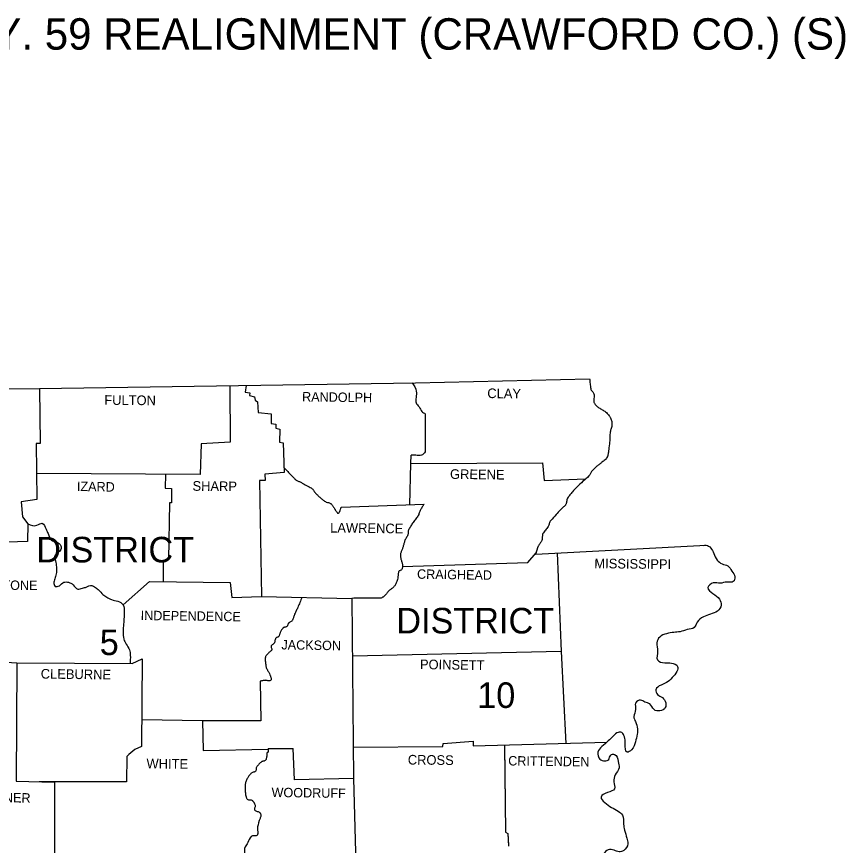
# Model space of a CAD drawing. Extents: x 6028666 to 6031787, y 5366484 to 5368484.
# Drawn here: x 6031401.8 to 6031771, y 5368078.3 to 5368447.7 of the extents above; entities that cross this region are included whole.
import ezdxf

# ---------------------------------------------------------------- set-up
doc = ezdxf.new("R2010")
doc.units = 0
doc.layers.add('2', color=7, linetype='Continuous')
doc.layers.add('R_Border', color=7, linetype='Continuous')

msp = doc.modelspace()

# ---------------------------------------------------------------- linework, layer by layer
at = {"layer": '2'}
for p, q in [((6031577.46, 5368248.49), (6031577.55, 5368252.19)), ((6031633.05, 5368208.19), (6031634.13, 5368211.51)), ((6031513.85, 5368121.6), (6031525.03, 5368121.6))]:
    msp.add_line(p, q, dxfattribs=at)
for points in [[(6031108.45, 5368281.69), (6031270.15, 5368281.59), (6031412.05, 5368281.89), (6031579.45, 5368284.49), (6031657.05, 5368286.29)], [(6031412.05, 5368281.89), (6031412.25, 5368257.49), (6031410.55, 5368257.39), (6031410.85, 5368232.49), (6031403.85, 5368231.49), (6031404.45, 5368224.79), (6031406.85, 5368221.69), (6031406.65, 5368213.79), (6031393.05, 5368213.29), (6031392.55, 5368201.09), (6031380.15, 5368200.69), (6031379.55, 5368185.89), (6031380.25, 5368184.69), (6031380.55, 5368161.09), (6031401.95, 5368159.69), (6031401.65, 5368107), (6031418.65, 5368106.5), (6031418.65, 5368052.9), (6031405.25, 5368051.9), (6031404.25, 5368040.1), (6031381.75, 5368040)], [(6031496.75, 5368283.21), (6031496.95, 5368257.99), (6031483.95, 5368257.29), (6031483.55, 5368243.69), (6031410.71, 5368244.1)], [(6031504.03, 5368283.32), (6031503.65, 5368280.29), (6031505.65, 5368279.99), (6031505.55, 5368278.79), (6031507.85, 5368278.29), (6031508.05, 5368276.69), (6031509.15, 5368275.99), (6031509.45, 5368271.19), (6031515.15, 5368270.59), (6031515.15, 5368266.29), (6031517.25, 5368265.99), (6031517.25, 5368264.29), (6031519.05, 5368263.79), (6031518.95, 5368257.99), (6031520.55, 5368257.69), (6031520.95, 5368244.59), (6031512.45, 5368243.79), (6031512.55, 5368240.99), (6031509.95, 5368240.89), (6031510.85, 5368189.29), (6031551.15, 5368188.39), (6031551.85, 5368108.2), (6031525.55, 5368107.5), (6031525.03, 5368121.6)], [(6031583.85, 5368270.69), (6031583.85, 5368253.79)], [(6031577.03, 5368230.16), (6031577.46, 5368248.49), (6031577.55, 5368248.49), (6031636.05, 5368248.79), (6031636.85, 5368240.99), (6031655.2, 5368241.66)], [(6031468.17, 5368243.78), (6031467.95, 5368237.59), (6031470.75, 5368237.39), (6031470.85, 5368230.99), (6031469.85, 5368230.99), (6031469.45, 5368205.79), (6031467.15, 5368204.79), (6031467.15, 5368195.91)], [(6031546.45, 5368229.09), (6031583.32, 5368230.38)], [(6031633.05, 5368208.19), (6031708.95, 5368212.09)], [(6031573.71, 5368202.68), (6031629.55, 5368204.49), (6031633.22, 5368208.72)], [(6031642.63, 5368208.69), (6031644.35, 5368164.79), (6031646.39, 5368123.83)], [(6031449.35, 5368185.51), (6031460.95, 5368195.99), (6031496.95, 5368195.49), (6031497.65, 5368188.79), (6031510.85, 5368189.29)], [(6031564.25, 5368188.59), (6031552.05, 5368188.59), (6031551.15, 5368188.39)], [(6031644.35, 5368164.79), (6031551.38, 5368162.67)], [(6031401.95, 5368159.69), (6031453.35, 5368159.39), (6031457.75, 5368161.49), (6031457.45, 5368122.4), (6031454.45, 5368121.1), (6031451.75, 5368118.8), (6031450.85, 5368117.9), (6031450.75, 5368106.7), (6031411.85, 5368106.7)], [(6031510.35, 5368151.5), (6031510.55, 5368133.9), (6031484.55, 5368133.8), (6031457.54, 5368134.3)], [(6031484.55, 5368133.8), (6031484.95, 5368120.7), (6031513.85, 5368121.21)], [(6031551.73, 5368122.19), (6031591.65, 5368122.4), (6031591.75, 5368123.8), (6031605.15, 5368124.8), (6031605.15, 5368122.7), (6031664.72, 5368124.33)], [(6031619.15, 5368123.08), (6031619.65, 5368084.2), (6031620.55, 5368083.6), (6031620.87, 5368078.06)], [(6031513.85, 5368121.6), (6031513.85, 5368119.9), (6031513.35, 5368119.8)], [(6031619.15, 5368122.7), (6031619.65, 5368084.2), (6031620.55, 5368083.6), (6031620.85, 5368078.4)], [(6031619.15, 5368122.7), (6031619.65, 5368084.2), (6031620.55, 5368083.6), (6031620.85, 5368078.4)], [(6031619.15, 5368122.7), (6031619.65, 5368084.2), (6031620.55, 5368083.6), (6031620.85, 5368078.4)], [(6031619.15, 5368122.7), (6031619.65, 5368084.2), (6031620.55, 5368083.6), (6031620.85, 5368078.4)], [(6031551.85, 5368108.2), (6031553.35, 5368053.4), (6031529.55, 5368053.3), (6031529.45, 5368051.1), (6031522.55, 5368050.7), (6031521.95, 5368039.3), (6031512.47, 5368039.3)]]:
    msp.add_lwpolyline(points, dxfattribs=at)
for points in [[(6031657.05, 5368286.29), (6031657.14, 5368285.19), (6031657.25, 5368284.09), (6031657.39, 5368282.99), (6031657.55, 5368281.89), (6031657.79, 5368281.27), (6031658.19, 5368280.71), (6031658.63, 5368280.17), (6031658.95, 5368279.59), (6031659.08, 5368278.58), (6031658.95, 5368277.48), (6031658.88, 5368276.39), (6031658.95, 5368275.88), (6031659.15, 5368275.39), (6031659.91, 5368274.41), (6031660.85, 5368273.59), (6031661.57, 5368273.12), (6031662.31, 5368272.7), (6031663.04, 5368272.28), (6031663.75, 5368271.79), (6031665.19, 5368270.51), (6031665.81, 5368269.76), (6031666.09, 5368269.35), (6031666.35, 5368268.89), (6031666.71, 5368268.05), (6031666.93, 5368267.19), (6031667, 5368266.34), (6031666.95, 5368265.49), (6031666.78, 5368264.62), (6031666.53, 5368263.75), (6031666.3, 5368262.87), (6031666.15, 5368261.99), (6031666.1, 5368261.02), (6031666.06, 5368260.04), (6031666.02, 5368259.07), (6031665.95, 5368258.09), (6031665.55, 5368254.69), (6031665.36, 5368253.13), (6031665.21, 5368252.35), (6031665.1, 5368251.97), (6031664.95, 5368251.59), (6031663.91, 5368250.21), (6031662.55, 5368249.09), (6031661.98, 5368248.64), (6031661.4, 5368248.2), (6031660.82, 5368247.76), (6031660.25, 5368247.29), (6031658.15, 5368245.19), (6031657.76, 5368244.65), (6031657.42, 5368244.07), (6031657.07, 5368243.5), (6031656.65, 5368242.99), (6031654.05, 5368240.59), (6031651.45, 5368238.09), (6031649.35, 5368235.89), (6031648.78, 5368235.23), (6031648.24, 5368234.54), (6031647.74, 5368233.82), (6031647.25, 5368233.09), (6031646.95, 5368232.34), (6031646.8, 5368231.51), (6031646.63, 5368230.7), (6031646.48, 5368230.33), (6031646.25, 5368229.99), (6031645.7, 5368229.42), (6031645.11, 5368228.89), (6031644.51, 5368228.36), (6031643.95, 5368227.79), (6031642.15, 5368225.79), (6031639.75, 5368223.09), (6031639.36, 5368222.48), (6031639.09, 5368221.78), (6031638.85, 5368221.07), (6031638.55, 5368220.39), (6031638.02, 5368219.6), (6031637.39, 5368218.85), (6031636.77, 5368218.1), (6031636.25, 5368217.29), (6031636.04, 5368216.58), (6031635.98, 5368215.8), (6031635.93, 5368215.02), (6031635.75, 5368214.29), (6031635.43, 5368213.67), (6031635.03, 5368213.08), (6031634.62, 5368212.49), (6031634.25, 5368211.89), (6031634.13, 5368211.51)], [(6031578.04, 5368284.47), (6031579.85, 5368280.69), (6031579.75, 5368277.99), (6031579.75, 5368275.49), (6031581.05, 5368273.79), (6031582.35, 5368271.69), (6031583.85, 5368270.69)], [(6031583.85, 5368253.79), (6031582.15, 5368252.19), (6031579.65, 5368252.19), (6031577.55, 5368252.19)], [(6031520.89, 5368246.7), (6031522.56, 5368244.94), (6031524.25, 5368243.19), (6031524.49, 5368242.95), (6031525.18, 5368242.22), (6031525.65, 5368241.75), (6031525.9, 5368241.51), (6031526.02, 5368241.4), (6031526.15, 5368241.29), (6031526.66, 5368240.95), (6031527.22, 5368240.7), (6031527.8, 5368240.46), (6031528.35, 5368240.19), (6031529.65, 5368239.44), (6031530.95, 5368238.69), (6031531.53, 5368238.39), (6031532.11, 5368238.12), (6031532.98, 5368237.67), (6031533.12, 5368237.58), (6031533.25, 5368237.49), (6031533.69, 5368237.09), (6031534.05, 5368236.59), (6031534.38, 5368236.07), (6031534.56, 5368235.82), (6031534.75, 5368235.59), (6031535.79, 5368234.53), (6031536.85, 5368233.49), (6031537.36, 5368233.04), (6031537.88, 5368232.61), (6031538.42, 5368232.2), (6031538.95, 5368231.79), (6031539.77, 5368231.37), (6031540.68, 5368231.08), (6031541.55, 5368230.75), (6031541.93, 5368230.51), (6031542.1, 5368230.36), (6031542.25, 5368230.19), (6031542.55, 5368229.78), (6031542.82, 5368229.35), (6031543.08, 5368228.92), (6031543.35, 5368228.49), (6031543.54, 5368228.22), (6031543.73, 5368227.92), (6031544.1, 5368227.34), (6031544.48, 5368226.81), (6031544.67, 5368226.58), (6031544.76, 5368226.48), (6031544.81, 5368226.44), (6031544.85, 5368226.39), (6031544.97, 5368226.32), (6031545.08, 5368226.31), (6031545.3, 5368226.44), (6031545.74, 5368227.16), (6031546.13, 5368228.16), (6031546.3, 5368228.66), (6031546.45, 5368229.09)], [(6031583.32, 5368230.38), (6031582.48, 5368229.17), (6031581.75, 5368227.89), (6031581.44, 5368227.2), (6031581.17, 5368226.48), (6031580.9, 5368225.77), (6031580.55, 5368225.09), (6031579.99, 5368224.27), (6031579.38, 5368223.48), (6031578.75, 5368222.7), (6031578.15, 5368221.89), (6031577.19, 5368220.38), (6031576.75, 5368219.6), (6031576.35, 5368218.79), (6031576.22, 5368218.28), (6031576.19, 5368217.75), (6031576.16, 5368217.21), (6031576.05, 5368216.69), (6031575.73, 5368215.99), (6031575.34, 5368215.3), (6031574.96, 5368214.61), (6031574.65, 5368213.89), (6031574.44, 5368213.2), (6031574.25, 5368212.49), (6031574.06, 5368211.79), (6031573.85, 5368211.09), (6031573.64, 5368210.49), (6031573.39, 5368209.9), (6031573.16, 5368209.3), (6031572.95, 5368208.69), (6031572.84, 5368208.08), (6031572.83, 5368207.45), (6031572.87, 5368206.81), (6031572.95, 5368206.19), (6031573.09, 5368205.56), (6031573.29, 5368204.94), (6031573.5, 5368204.32), (6031573.65, 5368203.69), (6031573.71, 5368203.13), (6031573.7, 5368202.54), (6031573.61, 5368201.96), (6031573.54, 5368201.68), (6031573.45, 5368201.39), (6031573.15, 5368201.05), (6031572.68, 5368200.84), (6031572.22, 5368200.63), (6031571.95, 5368200.29), (6031571.87, 5368199.94), (6031571.82, 5368199.58), (6031571.75, 5368198.85), (6031571.68, 5368198.11), (6031571.55, 5368197.39), (6031571.29, 5368196.39), (6031570.95, 5368195.39), (6031570.4, 5368194.33), (6031570.05, 5368193.85), (6031569.65, 5368193.39), (6031569.2, 5368192.99), (6031568.7, 5368192.63), (6031568.21, 5368192.28), (6031567.75, 5368191.89), (6031567.24, 5368191.34), (6031566.76, 5368190.75), (6031566.28, 5368190.15), (6031565.75, 5368189.59), (6031565.05, 5368189.04), (6031564.67, 5368188.81), (6031564.25, 5368188.59)], [(6031406.85, 5368221.69), (6031410.85, 5368220.99), (6031413.25, 5368221.89), (6031414.95, 5368219.29), (6031415.85, 5368217.29), (6031417.35, 5368214.39), (6031419.75, 5368213.49), (6031421.55, 5368211.89), (6031421.55, 5368210.19), (6031419.95, 5368208.59), (6031418.75, 5368206.99), (6031419.15, 5368205.09), (6031419.55, 5368202.49), (6031419.55, 5368199.99), (6031418.95, 5368197.69), (6031418.45, 5368195.59), (6031418.95, 5368193.79), (6031420.85, 5368194.09), (6031422.85, 5368195.59), (6031424.95, 5368195.59), (6031426.95, 5368194.49), (6031429.05, 5368192.59), (6031431.15, 5368192.99), (6031432.85, 5368193.49), (6031435.25, 5368194.19), (6031436.95, 5368193.29), (6031438.45, 5368192.09), (6031440.25, 5368190.19), (6031441.95, 5368188.99), (6031444.15, 5368187.89), (6031446.85, 5368187.19), (6031449.35, 5368185.49), (6031449.75, 5368182.59), (6031449.65, 5368180.09), (6031449.45, 5368176.99), (6031449.25, 5368173.59), (6031449.55, 5368170.29), (6031450.65, 5368168.09), (6031452.05, 5368165.49), (6031452.45, 5368163.09), (6031452.35, 5368159.29)], [(6031707.85, 5368211.99), (6031708.95, 5368212.09), (6031712.35, 5368208.49), (6031713.85, 5368205.49), (6031716.05, 5368203.79), (6031718.55, 5368202.89), (6031720.45, 5368200.59), (6031721.75, 5368198.09), (6031721.05, 5368195.89), (6031718.25, 5368195.69), (6031715.15, 5368195.19), (6031712.15, 5368195.29), (6031709.75, 5368193.29), (6031711.95, 5368190.59), (6031714.85, 5368188.09), (6031715.65, 5368185.39), (6031714.05, 5368182.79), (6031710.85, 5368181.39), (6031707.75, 5368180.19), (6031704.95, 5368177.79), (6031703.65, 5368175.49), (6031700.55, 5368174.49), (6031697.35, 5368173.59), (6031694.55, 5368173.29), (6031691.35, 5368172.69), (6031688.25, 5368171.19), (6031686.95, 5368168.59), (6031687.35, 5368164.89), (6031687.25, 5368160.99), (6031690.55, 5368159.69), (6031693.45, 5368159.59), (6031696.25, 5368158.09), (6031695.95, 5368155.9), (6031693.85, 5368153.1), (6031691.35, 5368150.9), (6031688.85, 5368149.8), (6031686.55, 5368147.7), (6031687.35, 5368145.6), (6031689.45, 5368144.2), (6031690.95, 5368141.9), (6031690.75, 5368139.8), (6031688.35, 5368138.3), (6031685.75, 5368138.9), (6031683.85, 5368141.4), (6031681.65, 5368142.2), (6031679.75, 5368143.1), (6031677.55, 5368141.8), (6031677.55, 5368138.9), (6031676.75, 5368135.8), (6031677.45, 5368133.5), (6031678.35, 5368130.3), (6031678.25, 5368127.9), (6031677.45, 5368124.5), (6031675.75, 5368121), (6031673.75, 5368119.9), (6031672.95, 5368123.7), (6031672.55, 5368126.8), (6031671.35, 5368128.6), (6031669.75, 5368128.7), (6031667.65, 5368127.2), (6031665.35, 5368124.9), (6031662.45, 5368122.4), (6031660.75, 5368119.9), (6031661.65, 5368116.8), (6031663.85, 5368116), (6031665.55, 5368116.6), (6031666.45, 5368118.6), (6031668.15, 5368118.9), (6031669.75, 5368115.8)], [(6031528.92, 5368188.89), (6031528.02, 5368186.63), (6031527.05, 5368184.39), (6031526.71, 5368183.64), (6031526.35, 5368182.89), (6031526, 5368182.14), (6031525.65, 5368181.39), (6031525.41, 5368180.75), (6031525.2, 5368180.09), (6031525, 5368179.43), (6031524.75, 5368178.79), (6031524.38, 5368178.33), (6031523.86, 5368177.99), (6031523.31, 5368177.67), (6031523.06, 5368177.5), (6031522.85, 5368177.29), (6031522.68, 5368176.97), (6031522.56, 5368176.59), (6031522.45, 5368176.21), (6031522.25, 5368175.89), (6031521.87, 5368175.69), (6031521.4, 5368175.61), (6031520.93, 5368175.52), (6031520.55, 5368175.29), (6031520.36, 5368175.06), (6031520.18, 5368174.83), (6031519.84, 5368174.34), (6031519.53, 5368173.82), (6031519.25, 5368173.29), (6031519.08, 5368172.85), (6031518.96, 5368172.39), (6031518.83, 5368171.93), (6031518.65, 5368171.49), (6031518.37, 5368171.23), (6031517.97, 5368171.08), (6031517.56, 5368170.93), (6031517.25, 5368170.69), (6031517.12, 5368170.45), (6031517.02, 5368170.18), (6031516.88, 5368169.6), (6031516.76, 5368169.01), (6031516.62, 5368168.61), (6031516.55, 5368168.49), (6031516.27, 5368168.18), (6031515.9, 5368167.9), (6031515.53, 5368167.62), (6031515.25, 5368167.29), (6031515.2, 5368166.82), (6031515.34, 5368166.28), (6031515.47, 5368165.75), (6031515.35, 5368165.29), (6031515.27, 5368165.2), (6031515.19, 5368165.11), (6031514.61, 5368164.59), (6031514.22, 5368164.26), (6031513.85, 5368163.89), (6031513.51, 5368163.52), (6031513.17, 5368163.15), (6031512.87, 5368162.75), (6031512.75, 5368162.53), (6031512.65, 5368162.29), (6031512.53, 5368161.2), (6031512.65, 5368160.09), (6031512.73, 5368159.36), (6031512.81, 5368158.63), (6031512.94, 5368157.91), (6031513.03, 5368157.55), (6031513.15, 5368157.19), (6031513.37, 5368156.75), (6031513.63, 5368156.33), (6031513.9, 5368155.92), (6031514.15, 5368155.5), (6031514.64, 5368154.4), (6031514.85, 5368153.85), (6031515.05, 5368153.3), (6031515.16, 5368152.94), (6031515.23, 5368152.56), (6031515.18, 5368152.19), (6031515.09, 5368152.03), (6031515.03, 5368151.96), (6031514.95, 5368151.9), (6031514.34, 5368151.66), (6031513.71, 5368151.72), (6031513.08, 5368151.87), (6031512.76, 5368151.91), (6031512.45, 5368151.9), (6031511.93, 5368151.81), (6031511.4, 5368151.72), (6031510.88, 5368151.62), (6031510.35, 5368151.5)], [(6031513.35, 5368119.8), (6031513.29, 5368118.96), (6031513.22, 5368118.14), (6031513.08, 5368117.31), (6031512.98, 5368116.9), (6031512.92, 5368116.7), (6031512.85, 5368116.5), (6031512.53, 5368116.13), (6031512.02, 5368115.95), (6031511.45, 5368115.82), (6031511.18, 5368115.73), (6031510.95, 5368115.6), (6031509.78, 5368114.56), (6031508.75, 5368113.4), (6031508.56, 5368112.92), (6031508.52, 5368112.38), (6031508.46, 5368111.85), (6031508.25, 5368111.4), (6031508.07, 5368111.24), (6031507.85, 5368111.13), (6031507.37, 5368110.99), (6031506.87, 5368110.85), (6031506.45, 5368110.6), (6031505.98, 5368110.12), (6031505.53, 5368109.62), (6031505.12, 5368109.08), (6031504.75, 5368108.5), (6031504.06, 5368107.08), (6031503.65, 5368105.6), (6031503.57, 5368104.1), (6031503.65, 5368102.6), (6031503.72, 5368101.73), (6031503.84, 5368100.88), (6031504.04, 5368100.03), (6031504.18, 5368099.61), (6031504.35, 5368099.2), (6031504.82, 5368098.79), (6031505.51, 5368098.68), (6031506.25, 5368098.6), (6031506.85, 5368098.3), (6031507.05, 5368098.07), (6031507.24, 5368097.83), (6031507.56, 5368097.34), (6031508.05, 5368096.3), (6031508.08, 5368095.78), (6031507.93, 5368095.23), (6031507.79, 5368094.69), (6031507.85, 5368094.2), (6031508.32, 5368093.76), (6031509.01, 5368093.52), (6031509.72, 5368093.27), (6031510.25, 5368092.8), (6031510.43, 5368092.5), (6031510.58, 5368092.2), (6031510.67, 5368091.9), (6031510.65, 5368091.6), (6031510.25, 5368090.3), (6031509.15, 5368086.6), (6031509.08, 5368085.98), (6031509.13, 5368085.36), (6031509.21, 5368084.73), (6031509.25, 5368084.1), (6031509.21, 5368083.54), (6031509.15, 5368083.27), (6031509.05, 5368083), (6031508.53, 5368082.62), (6031507.73, 5368082.61), (6031506.92, 5368082.62), (6031506.35, 5368082.3), (6031504.75, 5368079.6), (6031503.65, 5368077.7), (6031503.52, 5368077.39), (6031503.31, 5368076.45), (6031503.27, 5368075.82), (6031503.25, 5368075.2), (6031503.3, 5368074.75), (6031503.43, 5368074.3), (6031503.54, 5368073.85), (6031503.55, 5368073.4), (6031503.41, 5368073.03), (6031503.18, 5368072.69), (6031502.93, 5368072.35), (6031502.75, 5368072), (6031502.67, 5368071.48), (6031502.66, 5368070.93), (6031502.61, 5368070.4), (6031502.45, 5368069.9), (6031501.45, 5368068.1), (6031500.55, 5368066.4), (6031500.59, 5368065.9), (6031500.98, 5368065.41), (6031501.4, 5368064.91), (6031501.55, 5368064.4), (6031501.41, 5368063.7), (6031501.25, 5368063), (6031501.1, 5368062.44), (6031500.92, 5368061.89), (6031500.65, 5368060.8)], [(6031669.75, 5368115.8), (6031670.15, 5368112.9), (6031668.45, 5368109.8), (6031667.85, 5368106.7), (6031668.15, 5368103.6), (6031664.95, 5368101.9), (6031662.15, 5368099.9), (6031663.75, 5368097.5), (6031666.75, 5368095.3), (6031669.75, 5368093.6), (6031671.65, 5368091.9), (6031672.15, 5368087.8), (6031672.65, 5368085.2), (6031673.65, 5368081.6), (6031674.05, 5368079.1), (6031672.25, 5368076.1), (6031670.15, 5368075.5), (6031667.95, 5368076.2), (6031665.35, 5368076.4), (6031663.25, 5368074.4), (6031661.75, 5368071.6), (6031660.25, 5368068.8), (6031659.15, 5368066.4), (6031658.05, 5368063.8), (6031655.85, 5368060.8), (6031653.15, 5368060.3), (6031649.95, 5368059.5), (6031648.05, 5368057.3), (6031648.35, 5368053.6), (6031650.15, 5368051.1), (6031651.55, 5368048), (6031652.55, 5368045.3), (6031652.05, 5368041.9), (6031650.65, 5368039.4), (6031648.85, 5368037.9), (6031648.05, 5368034.7), (6031646.75, 5368032.3), (6031645.55, 5368031.5), (6031643.15, 5368031.7), (6031640.55, 5368032.2), (6031638.35, 5368032), (6031636.25, 5368030.9), (6031634.15, 5368031.6), (6031631.95, 5368034), (6031630.15, 5368035.8), (6031628.15, 5368036.5), (6031626.05, 5368035.4), (6031625.65, 5368032.1), (6031626.65, 5368028.7), (6031627.55, 5368024.1), (6031626.65, 5368021.3), (6031626.35, 5368016.7)]]:
    msp.add_spline(points, degree=3, dxfattribs=at)

# ---------------------------------------------------------------- texts
for s, height, rotation, p in [('CLAY', 4.299, 359.2258, (6031611.45, 5368277.69)), ('FULTON', 4.299, 359.4996, (6031440.85, 5368274.69)), ('RANDOLPH', 4.2, 359.2584, (6031528.95, 5368276.19)), ('GREENE', 4.301, 359.2361, (6031594.85, 5368241.69)), ('IZARD', 4.199, 358.9259, (6031428.65, 5368236.29)), ('SHARP', 4.299, 359.3905, (6031480.15, 5368236.39)), ('LAWRENCE', 4.301, 359.2678, (6031541.45, 5368217.79)), ('MISSISSIPPI', 4.2994, 359.3097, (6031659.15, 5368201.89)), ('CRAIGHEAD', 4.2, 359.1159, (6031580.15, 5368197.19)), ('STONE', 4.199, 359.4001, (6031391.75, 5368192.29)), ('INDEPENDENCE', 4.1992, 359.2188, (6031457.05, 5368178.79)), ('JACKSON', 4.199, 359.1352, (6031519.75, 5368165.69)), ('POINSETT', 4.299, 359.1987, (6031581.45, 5368156.9)), ('CLEBURNE', 4.299, 359.2535, (6031412.55, 5368152.7)), ('WHITE', 4.301, 359.3139, (6031459.65, 5368112.7)), ('CROSS', 4.299, 359.384, (6031576.05, 5368114.4)), ('CRITTENDEN', 4.2, 359.213, (6031620.75, 5368114)), ('FAULKNER', 4.2, 359.2486, (6031378.05, 5368097.8)), ('WOODRUFF', 4.199, 359.2748, (6031515.35, 5368099.9))]:
    msp.add_text(s, height=height, rotation=rotation, dxfattribs=at).set_placement(p)
for s, p in [('DISTRICT', (6031410.57, 5368204.44)), ('DISTRICT', (6031570.95, 5368172.79)), ('5', (6031438.84, 5368163.16)), ('10', (6031606.98, 5368139.6))]:
    msp.add_text(s, height=11.4, dxfattribs=at).set_placement(p)
at = {"layer": 'R_Border'}
msp.add_text('HWY. 59 REALIGNMENT (CRAWFORD CO.) (S)', height=14, dxfattribs=at).set_placement((6031360.27, 5368432.93))

doc.saveas('drawing.dxf')
